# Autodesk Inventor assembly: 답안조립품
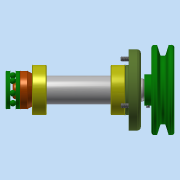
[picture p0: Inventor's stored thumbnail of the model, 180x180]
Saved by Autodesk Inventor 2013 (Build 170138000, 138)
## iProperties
Created: 2017-09
Part Number: 답안조립품
Document SubType Name: Assembly
Designer: dgall
Author: dgall
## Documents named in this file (12)
- C:\Users\dgall\Desktop\470907V1019\답안조립품.iam
- C:\Users\dgall\Desktop\470907V1019\V벨트풀리.ipt
- C:\Users\dgall\Desktop\470907V1019\멈춤나사 M3x8.ipt
- C:\Users\dgall\Desktop\470907V1019\베어링 6004.ipt
- C:\Users\dgall\Desktop\470907V1019\베어링 51202.ipt
- C:\Users\dgall\Desktop\470907V1019\본체.ipt
- C:\Users\dgall\Desktop\470907V1019\볼트 M4 x 12.ipt
- C:\Users\dgall\Desktop\470907V1019\어댑터슬리브.ipt
- C:\Users\dgall\Desktop\470907V1019\오일 실 20x35x7.ipt
- C:\Users\dgall\Desktop\470907V1019\축.ipt
- C:\Users\dgall\Desktop\470907V1019\커버.ipt
- C:\Users\dgall\Desktop\470907V1019\키 5 x 5 x 16.ipt
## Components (1 placed, 1 different names)
1. V벨트풀리:1
